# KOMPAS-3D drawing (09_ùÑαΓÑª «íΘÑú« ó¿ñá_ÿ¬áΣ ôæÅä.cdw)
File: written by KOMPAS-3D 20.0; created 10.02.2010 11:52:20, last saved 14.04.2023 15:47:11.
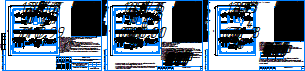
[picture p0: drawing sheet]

Sheets 1-3: A3, landscape

Document properties: Полное имя файла: \\s-tech\depts\Отдел_ПКО\Проекты\Типовые проекты МКД 2023\!Типовой проект\1_Типовой проект МКД_RS-485\09_Чертеж общего вида_Шкаф УСПД.cdw; Автор: Силов Дмитрий Дмитриевич; Организация: ЗАО ИТФ "Системы и Технологии"; Разработал: Воронина; Проверил: Тарасов; Утвердил: Шмончев; Форматы листов документа: 3xA3; Масса: 5.55816; Наименование: MES 30.20.15 Шкаф компактный распределительный

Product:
- Part/product: (unnamed)
  - Component: Рейка  | designation 123  | qty 4  | pos. 1  | Раздел спецификации: Детали

Title block, sheet 1: Наименование: Шкаф учета настненный для установки / счетчика; designation: ВЛСТ 1277.01.000 В0; Материал: Общий вид шкафа учета; scale: 1:4; sheet number: 1; Количество листов документа: 3; organisation: АО ГК / "Системы и Технологии"; Форматы листов документа: A3; stored path: Z:\!Оборудование СТ\Шкафы учета\Паспорта\На соглосовании\ВЛСТ 225.11.000\КД\СБ.cdw; cell 302: Система учета электроэнергии (с организацией удаленного / сбора данных) потребителей; cell 303: Типовой проект АСКУЭ многоквартирного / дома с использованием проводного / канала связи RS-485; cell 304: Чертеж общего вида шкафа УСПД; cell 320: Р
Title block, sheet 2: sheet number: 2; stored path: \\s-tech\depts\Отдел_ПКО\Проекты\Типовые проекты МКД 2023\!Типовой проект\1_Типовой проект МКД_RS-485\_Чертеж общего вида_Шкаф УСПД.cdw
Title block, sheet 3: sheet number: 3

Referenced files in \\Helios\отдел_пко\Общая папка Компас\_Addons\Signatures\: Signatures.lfr|Тарасов, Signatures.lfr, Signatures.lfr|Шмончев
Referenced files in C:\Program Files\ASCON\KOMPAS-3D V13\Libs\_Addons\Signatures\: Signatures.lfr
Referenced files: qlkzkl.frw, hsklda.frw, jndvba.frw
Referenced files in Y:\Общая папка Компас\_Addons\Signatures\: Signatures.lfr|Голдина, Signatures.lfr
Referenced files in \\s-tech\depts\Отдел_ПКО\Сотрудники\Голдина\: Devices GK.lfr
Referenced files in \\s-tech\depts\Отдел_ПКО\Сотрудники\Голдина\MES X.Y.Z Шкаф компактный распределительный 3D\: Винт для петли 202-0606 М6х6_5.m3d, Шайба Skiffy 003 0600 000 01_6.m3d, Гайка оц. М8 DIN 934.m3d, MES 30.20.15 Корпус_MES 30.30.15 00.000‘Ѓ Љ®аЇгб.m3d, Гайка оц. с фланцем, рифленая М8 DIN 6923_Hexagon Flange Nut DIN 6923 - M8 - C_4.m3d, MES 30.20 Дверь_MES 30.30 02.000‘Ѓ „ўҐам.m3d
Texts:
  Тарасов
  Шмончев
  Голдина
  Normal
  Centerline
  Outline
  Общий вид шкафа УСПД вариант 1
  Таблица 1 - Перечень основного оборудования
  № поз.
  Колич.
  Интеллектуальный контроллер SM160-02M
  Перемычка втычная Изолированная 2 полюса Красная Шаг 5,2мм
  Клеммник ("=24В") в составе:
  HMM.2/2+2GR(Ex), проходной зажим 2,5 кв.мм серый 2 ввод/2 вывода
  HMM.2/2+2(Ex)i, проходной зажим 2,5 кв.мм синий 2 ввод/2 вывода
  Блок питания 30 Вт (ВЛСТ 1000.10.002)
  Электронный переключатель фаз ПЭФ-301
  Коммутатор Planet ISW-800T
  Клеммник ("RS-485") в составе:
  HMT.2/2+2/PT(Ex)i, торцевой изолятор синий для НММ.2/2+2
  Клеммник ("N") в составе:
  Автоматический выключатель ВА47-29 2Р 6А х-ка С
  Преобразователь Ethernet/4xRS-485
  Проходной клеммный зажим серый ZHM500GR
  Проходной клеммный зажим синий ZHI500
  Торцевой изолятор серый ZHM501GR
  Профиль металлический DIN-рейка TS 35/7.5
  Кабель-канал перфорированный 40х60 "ИМПАКТ"
  BTO, Торцевой фиксатор 5мм
  Шина РЕ "земля" на DIN-изоляторе ШНИ-6х9-18-Д-Ж
  Клеммник ("RS-485 сч. ВРУ") в составе:
  ХТ2
  ХТ1
  QF1, QF2
  Шкаф распределительный MES 50.50.21
  Кабельный ввод М16
  Кабельный ввод М12
  Кабельный ввод М25 (п. 7)
  Кабельный ввод М32
  шт.
  не показана
  Общий вид шкафа УСПД вариант 3
  Общий вид шкафа УСПД вариант 2
  Таблица 2 - Перечень основного оборудования
  Клеммник ("L,N") в составе:
  Клеммник ("=24В для АРК") в составе (max 3 линии):
  ХТ3
  ХТ4
  Кабельный ввод М25 (п. 7, п.15)
  Таблица 3 - Перечень основного оборудования
  Преобразователь линии RS-485/CAN (ВЛСТ 217.00.000-04)
  Шкаф распределительный MES 50.40.21
  Кабельный ввод М25
  1. Шкаф УСПД разработан для МКД с этажностью - 14-18 (щит со счетчиками на площадке этажа,
  активная разветвительная коробка RS-485).
  2. Позиции указаны согласно Таблице 2.
  3. Размеры указаны для справок.
  4. Шкаф показан с открытой дверцей.
  5. Для ввода кабелей в шкаф просверлить отверстия в панели кабельного ввода.
  6. Для герметизации отверстий для ввода кабелей использовать кабельные вводы (поз. 18-21).
  7. Для линий RS-485 используется кабельный ввод М25. Количество кабельных вводов зависит
  от приходящих кабельных линий RS-485.
  8. При монтаже оборудования руководствоваться соответствующими разделами эксплуатационной
  документации оборудования.
  9. Количество преобразователей Ethernet/4xRS-485 зависит от количества линий RS-485.
  10. Если количество преобразователей Ethernet/4хRS-485 больше 5 шт, то требуется увеличение
  мощности блока питания.
  11. Количество клеммных сборок "RS-485" зависит от количества преобразователей Ethernet/
  12. Выбор блока питания для питания АРК
  1. Шкаф УСПД разработан для МКД с этажностью - 9, МКД с этажностью - 14-18 (щит со
  счетчиками на площадке этажа, пассивная разветвительная коробка RS-485).
  2. Позиции указаны согласно Таблице 1.
  6. Для герметизации отверстий для ввода кабелей использовать кабельные вводы (поз. 16-19).
  от количества приходящих кабельных линий RS-485.
  13. Подключение питания для АРК осуществить кабелем Hyperline FTP4-C5E-SOLID-OUTDOOR-40.
  Расключение в клеммник осуществить скруткой двух жил кабеля.
  14. Количество клемм в клеммнике XT4 меняется в зависимости от количества питающих линий АРК.
  15. Кабельный ввод М25 используется для линий АРК. Количество кабельных вводов зависит
  от приходящих кабельных линий АРК.
  Блок питания
  Мощность блока, Вт
  Количество АРК, шт
  DPP30-24
  DPP50-24
  DPP100-24
  1. Шкаф УСПД разработан для МКД с этажностью - до 5.
  6. Для герметизации отверстий для ввода кабелей использовать кабельные вводы (поз. 17-20).
  7. При монтаже оборудования руководствоваться соответствующими разделами эксплуатационной
  8. Выбор блока питания для питания АРК
  9. Подключение питания для АРК осуществить кабелем Hyperline FTP4-C5E-SOLID-OUTDOOR-40.
  10. Количество клемм в клеммнике XT4 меняется в зависимости от количества питающих линий АРК.
  11. Кабельный ввод М25 используется для линий АРК. Количество кабельных вводов зависит от приходящих
  кабельных линий АРК.
  PLANET
  Лицевая 4.png
  DSP30-24
  Лицевая панель.png
  POLYLINE_STYLE_0.18_RGB_0_0_0
  POLYLINE_STYLE_0.25_RGB_0_0_0
  Стили документа
  Рейка
  2D_Doc-graphic.lyt,1.000000-0-170951471925
  2D_Doc-graphic.lyt,1.000000-0-170951472025
  2D_Doc-graphic.lyt,1.000000-0-170951472125
  2D_Doc-graphic.lyt,1.000000-0-170951472225
  Винт для петли 202-0606 М6х6
  Шайба Skiffy 003 0600 000 01
  Гайка оц. М8 DIN 934
  MES 30.20.15 Корпус_MES 30.30.15 00.000‘Ѓ Љ®аЇгб
  Гайка оц. с фланцем, рифленая М8 DIN 6923_Hexagon Flange Nut DIN 6923 - M8 - C
  MES 30.20 Дверь_MES 30.30 02.000‘Ѓ „ўҐам
  ANSI37
  Разраб.
  Н.контр.
  Утв.
  Общий вид
  шкафа учёта
  Воронина
  03 Рабочие чертежи основного комплекта. ГОСТ 21.101-97 Ф3
  05 Чертежи строительных изделий. Посл. листы. ГОСТ Р 21.1101-2009 Ф6
Dimensions and other numbers on the sheet: 3с5; 3,0; 5и0; 3и3; 35; 6; 4; 3; 2; 1; 5; 9; 8; 7; 13; 14; 12; 11; 10; 1 шт.; 2 шт.; 1 компл.; 1-5 шт.; 1 м; 0,5 м; 19 шт.; 2 компл.; 15; 17; 16; 18; 19; 21 шт.; 20; 21; 500; 16 шт.; 400; 4xRS-485.; 30; 50; 100; 37; 340.00.png; 123; 22; 23; 24; 25; 26; 27; 1:4; 03.23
